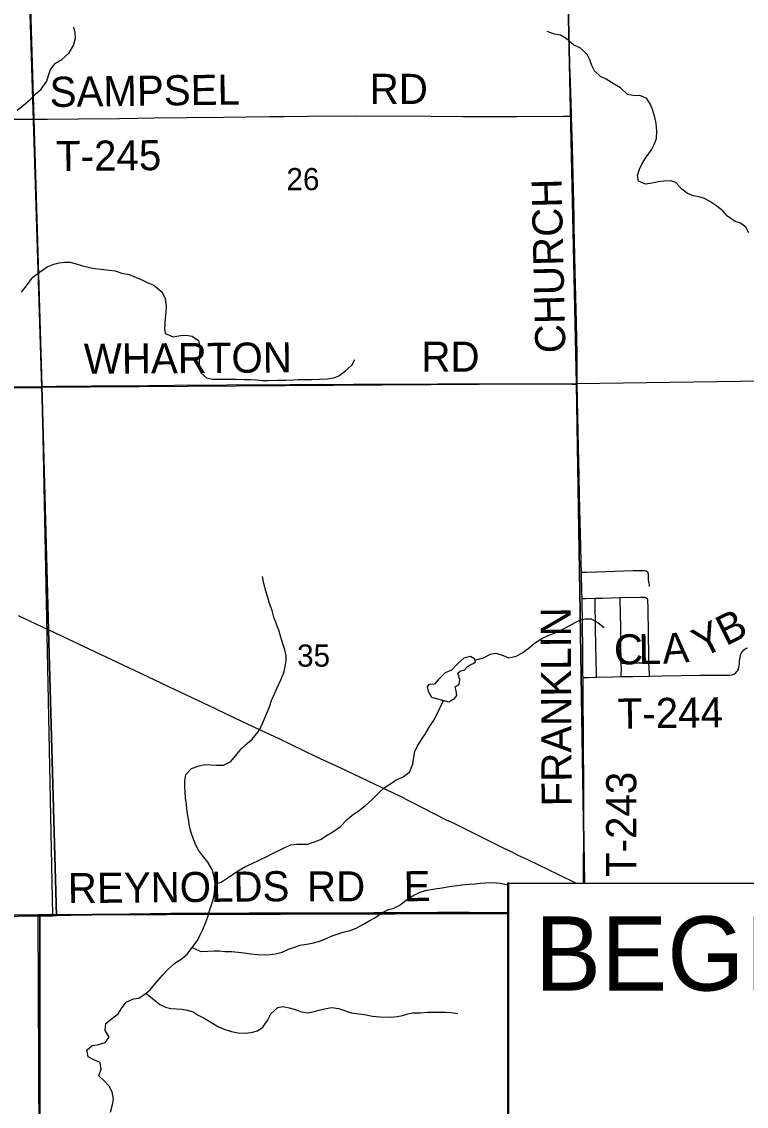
# Model space of a CAD drawing. Extents: x 0 to 34, y 0 to 22.
# Drawn here: x 3.396 to 4.763, y 17.915 to 19.961 of the extents above; entities that cross this region are included whole.
import ezdxf

# ---------------------------------------------------------------- set-up
doc = ezdxf.new("R2010")
doc.units = 0
for name, color, linetype in [('Default', 7, 'Continuous'), ('GM_X_Minor_Lake', 7, 'Continuous'), ('GM_X_Minor_River', 7, 'Continuous'), ('GM_X_Section', 7, 'Continuous'), ('GM_X_Section_Text', 7, 'Continuous'), ('GM_X_State_Route', 7, 'Continuous'), ('GM_X_Township_Road', 7, 'Continuous'), ('GM_X_Township_Road_Text', 7, 'Continuous')]:
    doc.layers.add(name, color=color, linetype=linetype)

msp = doc.modelspace()

# ---------------------------------------------------------------- linework, layer by layer
at = {"layer": 'Default'}
for points in [[(3.3888, 18.2738), (3.4301, 18.2744), (3.4535, 18.2747), (3.4612, 18.275), (3.4463, 18.8138), (3.4336, 19.2731), (3.4185, 19.7774), (3.4027, 20.3001)], [(3.4027, 20.3001), (3.4185, 19.7774), (3.4336, 19.2731), (3.4463, 18.8138), (3.4612, 18.275), (3.4874, 18.2757), (3.5278, 18.2766), (3.5774, 18.2768), (3.5992, 18.2774), (3.6768, 18.2782), (3.7478, 18.2787), (3.7636, 18.2786), (3.7693, 18.2786), (3.7965, 18.2787), (3.8251, 18.2793), (3.8625, 18.2791), (3.8836, 18.2793), (3.9241, 18.2791), (3.9547, 18.2791), (3.9763, 18.2791), (4.0287, 18.2792), (4.0598, 18.2796), (4.0753, 18.2798), (4.1094, 18.2798), (4.1498, 18.2796), (4.1807, 18.2803), (4.2397, 18.2802), (4.3145, 18.28), (4.3145, 18.3355), (6.2148, 18.3355)], [(3.4297, 17.7382), (3.4301, 18.2744), (3.3888, 18.2738)], [(4.3145, 17.662), (4.3145, 18.28), (4.2397, 18.2802), (4.1807, 18.2803), (4.1498, 18.2796), (4.1094, 18.2798), (4.0753, 18.2798), (4.0598, 18.2796), (4.0287, 18.2792), (3.9763, 18.2791), (3.9547, 18.2791), (3.9241, 18.2791), (3.8836, 18.2793), (3.8625, 18.2791), (3.8251, 18.2793), (3.7965, 18.2787), (3.7693, 18.2786), (3.7636, 18.2786), (3.7478, 18.2787), (3.6768, 18.2782), (3.5992, 18.2774), (3.5774, 18.2768), (3.5278, 18.2766), (3.4874, 18.2757), (3.4612, 18.275), (3.4535, 18.2747), (3.4301, 18.2744), (3.4297, 17.7382)]]:
    msp.add_lwpolyline(points, dxfattribs=at)
msp.add_lwpolyline([(4.3145, 18.3355), (4.3121, 18.3355), (4.3121, 17.6612), (6.2145, 17.6612), (6.2145, 17.662), (4.3145, 17.662)], close=True, dxfattribs=at)
at = {"layer": 'GM_X_Minor_Lake'}
for points in [[(4.2018, 18.6777), (4.2121, 18.6841), (4.2163, 18.6894), (4.2156, 18.6985), (4.2133, 18.7061), (4.2209, 18.711), (4.2225, 18.7201), (4.2188, 18.7319), (4.223, 18.7356), (4.2313, 18.7382), (4.237, 18.7443), (4.2431, 18.7484), (4.2477, 18.7499), (4.2519, 18.7533), (4.25, 18.7587), (4.2421, 18.7632), (4.2299, 18.7599), (4.2185, 18.7497), (4.2066, 18.7372), (4.1945, 18.7327), (4.1815, 18.7191), (4.1743, 18.7112), (4.164, 18.7105), (4.1606, 18.7059), (4.1624, 18.698), (4.1685, 18.6862)], [(4.1685, 18.6862), (4.2018, 18.6777)]]:
    msp.add_lwpolyline(points, dxfattribs=at)
at = {"layer": 'GM_X_Minor_River'}
for points in [[(3.3872, 19.7938), (3.3986, 19.8024), (3.4131, 19.8149), (3.4227, 19.8243), (3.4326, 19.833), (3.4429, 19.8482), (3.4463, 19.8591), (3.4502, 19.8701), (3.4597, 19.8822), (3.4712, 19.8894), (3.4856, 19.9015), (3.4937, 19.9155), (3.4971, 19.9295), (3.4964, 19.9397), (3.4938, 19.95)], [(4.63, 19.6575), (4.6205, 19.6602), (4.6068, 19.6599), (4.5966, 19.6588), (4.5852, 19.6558), (4.5723, 19.654), (4.559, 19.6598), (4.5576, 19.6704), (4.561, 19.6825), (4.5664, 19.6928), (4.574, 19.7049), (4.5836, 19.7189), (4.5886, 19.7287), (4.5932, 19.7405), (4.594, 19.7534), (4.5926, 19.7685), (4.5903, 19.7807), (4.5855, 19.7948), (4.5817, 19.8043), (4.5753, 19.8157), (4.5621, 19.8214), (4.5522, 19.8207), (4.5386, 19.8231), (4.5253, 19.8357), (4.5132, 19.8429), (4.4981, 19.8521), (4.4879, 19.8571), (4.4762, 19.8678), (4.4713, 19.8777), (4.4675, 19.8883), (4.4627, 19.8986), (4.4498, 19.9108), (4.4369, 19.9169), (4.4237, 19.928), (4.412, 19.9353), (4.401, 19.9368), (4.387, 19.9422)], [(4.7676, 19.562), (4.762, 19.573), (4.7518, 19.5803), (4.7415, 19.5834), (4.7275, 19.5937), (4.7185, 19.604), (4.7071, 19.6127), (4.6939, 19.6215), (4.6837, 19.6269), (4.6738, 19.63), (4.6632, 19.6323), (4.6515, 19.6365), (4.6413, 19.6446), (4.63, 19.6575)], [(3.3951, 19.4502), (3.4065, 19.4646), (3.4168, 19.4786), (3.4294, 19.4884), (3.4435, 19.4982), (3.4564, 19.5035), (3.4663, 19.5057), (3.4769, 19.5071), (3.4868, 19.5067), (3.4985, 19.504), (3.5106, 19.5002), (3.5235, 19.4967), (3.5341, 19.4951), (3.5448, 19.4939), (3.5614, 19.4916), (3.5721, 19.4904), (3.5846, 19.4865), (3.5982, 19.4834), (3.6107, 19.4788), (3.6209, 19.4742), (3.6327, 19.4688), (3.6448, 19.4634), (3.6607, 19.4501), (3.6663, 19.4387), (3.6681, 19.4227), (3.6677, 19.4125), (3.6665, 19.4011), (3.6649, 19.3821), (3.6667, 19.3726), (3.6815, 19.3661), (3.6952, 19.3687), (3.7058, 19.369), (3.7175, 19.3671), (3.7293, 19.359), (3.7319, 19.3469), (3.731, 19.3313), (3.7306, 19.3214), (3.7306, 19.3112), (3.7335, 19.2983), (3.7441, 19.2887), (3.7566, 19.2864), (3.7707, 19.286), (3.7801, 19.2863), (3.7999, 19.2862), (3.8154, 19.2857), (3.8276, 19.2857), (3.8386, 19.2849), (3.8499, 19.284), (3.8602, 19.2836), (3.878, 19.2843), (3.894, 19.2842), (3.9076, 19.2853), (3.9175, 19.2856), (3.9304, 19.2859), (3.9429, 19.2859), (3.9577, 19.2862), (3.9721, 19.2869), (3.9843, 19.2891), (3.9938, 19.2925), (4.0067, 19.3019), (4.0186, 19.3128), (4.0243, 19.3231)], [(3.5213, 18.0083), (3.5187, 18.0205), (3.5287, 18.0295), (3.5385, 18.031), (3.553, 18.0351), (3.5606, 18.0449), (3.5535, 18.0579), (3.5547, 18.0712), (3.5676, 18.0817), (3.5775, 18.0893), (3.584, 18.0991), (3.5928, 18.1112), (3.6065, 18.1172), (3.6167, 18.1187), (3.6285, 18.127), (3.638, 18.1345), (3.6487, 18.1478), (3.6621, 18.1625), (3.6705, 18.1723), (3.6846, 18.1848), (3.6983, 18.1935), (3.7086, 18.2021), (3.7193, 18.2169), (3.7273, 18.2275), (3.7323, 18.2381), (3.7372, 18.2483), (3.7434, 18.2623), (3.7468, 18.2722), (3.7503, 18.2832), (3.753, 18.293), (3.7569, 18.304), (3.7596, 18.3165), (3.7604, 18.326), (3.7608, 18.3355), (3.7586, 18.3477), (3.7549, 18.3613), (3.747, 18.3754), (3.7371, 18.388), (3.7292, 18.3979), (3.724, 18.4074), (3.7198, 18.4188), (3.7157, 18.4314), (3.7124, 18.4424), (3.7102, 18.4568), (3.7079, 18.4701), (3.7065, 18.4838), (3.705, 18.4963), (3.7043, 18.5077), (3.7036, 18.518), (3.7033, 18.5275), (3.7052, 18.5404), (3.7159, 18.5517), (3.7307, 18.557), (3.7421, 18.5596), (3.7528, 18.5591), (3.763, 18.5583), (3.7767, 18.5582), (3.7904, 18.5654), (3.8022, 18.5794), (3.8106, 18.5896), (3.8209, 18.5994), (3.8304, 18.607), (3.8418, 18.6209), (3.8472, 18.6312), (3.853, 18.6444), (3.858, 18.6565), (3.8629, 18.6683), (3.8668, 18.68), (3.8729, 18.6929), (3.8779, 18.7043), (3.8848, 18.7191), (3.8906, 18.7342), (3.8929, 18.7444), (3.8945, 18.7558), (3.8945, 18.7653), (3.8923, 18.7756), (3.8886, 18.7874), (3.8848, 18.7995), (3.8807, 18.8128), (3.8751, 18.8273), (3.8717, 18.8372), (3.868, 18.8497), (3.8635, 18.863), (3.8598, 18.8744), (3.856, 18.8862), (3.8527, 18.9007), (3.8497, 18.914)], [(4.2508, 18.7564), (4.2671, 18.7605), (4.2804, 18.7676), (4.2899, 18.7698), (4.3039, 18.7648), (4.3149, 18.761), (4.3286, 18.764), (4.3392, 18.7696), (4.3506, 18.7775), (4.3632, 18.7881), (4.3784, 18.7979), (4.391, 18.8035), (4.4062, 18.8099), (4.4165, 18.8148), (4.4271, 18.8204), (4.4401, 18.8276), (4.4499, 18.8321), (4.4594, 18.8343), (4.4701, 18.8343), (4.4829, 18.827), (4.4946, 18.8178)], [(3.7607, 18.3342), (3.7722, 18.3377), (3.7855, 18.3464), (3.7954, 18.3532), (3.8061, 18.3603), (3.8182, 18.3671), (3.8293, 18.3724), (3.8437, 18.3791), (3.857, 18.3855), (3.8703, 18.3923), (3.881, 18.3972), (3.8924, 18.4028), (3.9034, 18.4077), (3.9141, 18.4095), (3.9235, 18.4091), (3.9346, 18.4094), (3.9478, 18.4136), (3.9593, 18.4181), (3.9718, 18.426), (3.9825, 18.4324), (3.9966, 18.4422), (4.0091, 18.455), (4.019, 18.4641), (4.0305, 18.4712), (4.0434, 18.4814), (4.0564, 18.4927), (4.0701, 18.5067), (4.08, 18.5162), (4.0914, 18.5233), (4.1017, 18.5297), (4.1142, 18.5357), (4.1276, 18.5448), (4.1337, 18.5603), (4.1357, 18.5732), (4.1376, 18.5838), (4.1415, 18.5937), (4.1502, 18.6065), (4.1567, 18.6164), (4.1659, 18.6315), (4.1724, 18.6421), (4.1782, 18.6523), (4.1915, 18.6803)], [(3.7173, 18.2141), (3.7336, 18.2066), (3.7469, 18.2073), (3.7587, 18.208), (3.7682, 18.2079), (3.7788, 18.2071), (3.7913, 18.2067), (3.8042, 18.2055), (3.8152, 18.2043), (3.8281, 18.2027), (3.8398, 18.2011), (3.8546, 18.2003), (3.8645, 18.201), (3.8748, 18.2025), (3.8873, 18.2058), (3.8991, 18.2111), (3.9101, 18.2152), (3.9211, 18.2186), (3.9333, 18.2208), (3.9439, 18.2226), (3.9583, 18.2264), (3.9686, 18.2305), (3.9812, 18.2361), (3.9926, 18.2402), (4.0024, 18.2432), (4.0153, 18.2466), (4.0264, 18.2507), (4.0408, 18.2586), (4.0526, 18.265), (4.0621, 18.2703), (4.0762, 18.2801), (4.088, 18.2861), (4.0975, 18.2883), (4.1093, 18.2943), (4.1188, 18.3015), (4.1344, 18.3124), (4.1477, 18.3188), (4.1599, 18.3226), (4.1751, 18.3248), (4.1891, 18.327), (4.2024, 18.3296), (4.2119, 18.3307), (4.2263, 18.3325), (4.24, 18.3336), (4.251, 18.3343), (4.2605, 18.3354), (4.2708, 18.3364), (4.2844, 18.3371), (4.2984, 18.3355), (4.3136, 18.3324), (4.3145, 18.332)], [(3.6302, 18.1283), (3.6418, 18.1186), (3.6565, 18.1071), (3.6671, 18.1021), (3.6773, 18.0994), (3.688, 18.0986), (3.6978, 18.0978), (3.7081, 18.0962), (3.719, 18.0928), (3.7289, 18.087), (3.7399, 18.0809), (3.7554, 18.0717), (3.766, 18.0656), (3.7788, 18.0598), (3.7913, 18.056), (3.8042, 18.0536), (3.816, 18.0528), (3.8285, 18.0539), (3.8403, 18.0573), (3.8506, 18.064), (3.8594, 18.0765), (3.8659, 18.0894), (3.8788, 18.1011), (3.8891, 18.1029), (3.9001, 18.1006), (3.9095, 18.0983), (3.9236, 18.0933), (3.9361, 18.0913), (3.9475, 18.0936), (3.957, 18.0962), (3.9668, 18.0988), (3.9805, 18.1014), (3.9934, 18.099), (4.0044, 18.0956), (4.0173, 18.0913), (4.0317, 18.0893), (4.0427, 18.0882), (4.0578, 18.085), (4.0711, 18.0838), (4.0939, 18.083), (4.1041, 18.0841), (4.1144, 18.0863), (4.1239, 18.0893), (4.1337, 18.0911), (4.1482, 18.0914), (4.1611, 18.0921), (4.1721, 18.0921), (4.1846, 18.0924), (4.1956, 18.0923), (4.2062, 18.0915), (4.2184, 18.09)], [(3.563, 17.9037), (3.5668, 17.9181), (3.5688, 17.9284), (3.5662, 17.9424), (3.5609, 17.9527), (3.5522, 17.9622), (3.5413, 17.9722), (3.5459, 17.9847), (3.5437, 17.9976), (3.5316, 18.0026), (3.5213, 18.0083)]]:
    msp.add_lwpolyline(points, dxfattribs=at)
at = {"layer": 'GM_X_Section'}
for points in [[(3.4017, 20.2979), (3.4336, 19.2705), (2.4218, 19.2622), (2.3914, 20.2927)], [(4.4204, 20.2835), (4.4424, 19.2777), (3.4336, 19.2705), (3.4017, 20.2979)], [(5.4429, 20.296), (5.4558, 19.2921), (4.4424, 19.2777), (4.4204, 20.2835)], [(5.4633, 18.3355), (5.4558, 19.2921), (4.4424, 19.2777), (4.4577, 18.3355)], [(4.4577, 18.3355), (4.4424, 19.2777), (3.4336, 19.2705), (3.4536, 18.2761), (4.3145, 18.2784), (4.3145, 18.3355)], [(3.4336, 19.2705), (3.4536, 18.2761), (3.4263, 18.2757), (2.4434, 18.2628), (2.4218, 19.2622)], [(2.4116, 18.261), (2.4434, 18.2628), (3.4263, 18.2757), (3.4308, 17.2748), (2.406, 17.2639)], [(4.3145, 18.2784), (3.4536, 18.2761), (3.4263, 18.2757), (3.4308, 17.2748), (4.4385, 17.29), (4.4398, 17.662), (4.3145, 17.662)]]:
    msp.add_lwpolyline(points, close=True, dxfattribs=at)
at = {"layer": 'GM_X_State_Route'}
msp.add_line((3.4456, 18.8137), (3.3898, 18.8402), dxfattribs=at)
msp.add_lwpolyline([(4.4409, 18.3355), (4.4076, 18.352), (4.3714, 18.3698), (4.352, 18.3793), (4.3439, 18.3828), (4.3325, 18.3876), (4.3199, 18.3946), (4.306, 18.4012), (4.2896, 18.4095), (4.2528, 18.4272), (4.2114, 18.4481), (4.1974, 18.4547), (4.1531, 18.4772), (4.1088, 18.4997), (4.0613, 18.5227), (3.9966, 18.5532), (3.9515, 18.5741), (3.8815, 18.6077), (3.8477, 18.6236), (3.8112, 18.6408), (3.7495, 18.6702), (3.6736, 18.7059), (3.6203, 18.7314), (3.522, 18.7779), (3.4465, 18.8133), (3.4456, 18.8137)], dxfattribs=at)
at = {"layer": 'GM_X_Township_Road'}
for points in [[(4.4332, 19.7821), (4.4329, 19.7864), (4.4314, 19.8268), (4.429, 19.8983), (4.428, 19.948), (4.4267, 20.0039), (4.4241, 20.0971), (4.4225, 20.1624), (4.4203, 20.2338), (4.4194, 20.2711), (4.4194, 20.2841)], [(3.4445, 19.7769), (3.5028, 19.7773), (3.5805, 19.7782), (3.6458, 19.779), (3.708, 19.7798), (3.7764, 19.7807), (3.8635, 19.7819), (3.8915, 19.782), (3.935, 19.7825), (4.0252, 19.7829), (4.1683, 19.7822), (4.2273, 19.782), (4.33, 19.7819), (4.417, 19.7823), (4.4264, 19.7821), (4.4332, 19.7821)], [(3.2383, 19.7764), (3.2479, 19.7766), (3.2634, 19.7769), (3.3877, 19.777), (3.4187, 19.7769)], [(3.4187, 19.7769), (3.4375, 19.7768), (3.4445, 19.7769)], [(4.4438, 19.277), (4.4434, 19.3343), (4.4421, 19.3934), (4.44, 19.4896), (4.4386, 19.5477), (4.4382, 19.5725), (4.438, 19.5877), (4.4381, 19.5938), (4.4362, 19.6683), (4.435, 19.7243), (4.4332, 19.7821)], [(3.1716, 19.2703), (3.1803, 19.2705), (3.1989, 19.2711), (3.2331, 19.2711), (3.2952, 19.2714), (3.3605, 19.2717), (3.4338, 19.2725)], [(3.4338, 19.2725), (3.4506, 19.2727), (3.4616, 19.2728)], [(3.4616, 19.2728), (3.5283, 19.2737), (3.5873, 19.2739), (3.684, 19.2752), (3.7832, 19.2753), (3.9013, 19.2765), (3.9145, 19.2765), (3.9261, 19.2765), (3.9634, 19.2766), (4.0098, 19.2765), (4.0217, 19.2766), (4.0398, 19.2766), (4.0599, 19.2768), (4.0899, 19.277), (4.1799, 19.2776), (4.2451, 19.2778), (4.3698, 19.2776), (4.4344, 19.277), (4.4438, 19.277)], [(4.4529, 18.8723), (4.4524, 18.8844), (4.4519, 18.9224), (4.4514, 18.9397), (4.4504, 18.9708), (4.4492, 19.0174), (4.4482, 19.0671), (4.4474, 19.1044), (4.4461, 19.1572), (4.4438, 19.277)], [(4.4519, 18.9224), (4.4613, 18.9223), (4.4801, 18.9226), (4.5488, 18.9253), (4.5706, 18.9251), (4.5737, 18.9245), (4.5762, 18.9228), (4.5775, 18.92), (4.5778, 18.9169), (4.5778, 18.9075), (4.5781, 18.9044), (4.5793, 18.8983), (4.5797, 18.8952)], [(4.4529, 18.8723), (4.4602, 18.8726), (4.4778, 18.8731), (4.4912, 18.8735), (4.5247, 18.8744), (4.5626, 18.8754), (4.5705, 18.8752), (4.5721, 18.8748), (4.573, 18.8744), (4.5738, 18.8739), (4.5746, 18.8733), (4.5755, 18.8725)], [(4.455, 18.7238), (4.4546, 18.7295), (4.4543, 18.7657), (4.4536, 18.834), (4.4531, 18.862), (4.4529, 18.8723)], [(4.48, 18.7241), (4.4799, 18.7311), (4.4793, 18.756), (4.4784, 18.8153), (4.4778, 18.8682), (4.4778, 18.8731)], [(4.5269, 18.7252), (4.5269, 18.731), (4.527, 18.7373), (4.5268, 18.7503), (4.5259, 18.7904), (4.5257, 18.8185), (4.5248, 18.8685), (4.5247, 18.8744)], [(4.58, 18.7263), (4.5798, 18.73), (4.5791, 18.7513), (4.5789, 18.7688), (4.578, 18.8021), (4.5774, 18.858), (4.577, 18.8665), (4.5766, 18.8698), (4.5755, 18.8725)], [(4.48, 18.7241), (4.5111, 18.7248), (4.5269, 18.7252), (4.5484, 18.7257), (4.58, 18.7263), (4.6042, 18.7267), (4.6756, 18.7277), (4.7128, 18.7277), (4.7284, 18.7277), (4.7315, 18.7279), (4.7345, 18.7285), (4.7375, 18.7293), (4.7403, 18.7306), (4.7428, 18.7324), (4.7449, 18.7346), (4.7466, 18.7371), (4.7479, 18.7399), (4.7487, 18.7429), (4.7493, 18.7459), (4.7497, 18.7491), (4.7501, 18.7553), (4.7508, 18.7615), (4.7514, 18.7645), (4.7523, 18.7675), (4.7535, 18.7703), (4.7552, 18.7729), (4.7572, 18.7753), (4.7596, 18.7772), (4.7623, 18.7787), (4.7652, 18.7797)], [(4.5268, 18.7503), (4.5339, 18.7505), (4.5582, 18.7511), (4.5643, 18.7512), (4.5791, 18.7513)], [(4.455, 18.7238), (4.4646, 18.7239), (4.477, 18.724), (4.48, 18.7241)], [(4.4556, 18.3355), (4.4558, 18.346), (4.4563, 18.4393), (4.456, 18.5108), (4.4558, 18.6071), (4.4551, 18.6942), (4.4551, 18.7153), (4.455, 18.7238)], [(3.0684, 18.2709), (3.0845, 18.2708), (3.143, 18.2718), (3.1927, 18.2718), (3.2516, 18.2718), (3.3075, 18.2723), (3.389, 18.2733), (3.4303, 18.2739)], [(3.4303, 18.2739), (3.4537, 18.2742), (3.4614, 18.2744)], [(3.4614, 18.2744), (3.4876, 18.2751), (3.528, 18.2761), (3.5776, 18.2763), (3.5994, 18.2768), (3.677, 18.2776), (3.748, 18.2781), (3.7638, 18.2781), (3.7695, 18.278), (3.7967, 18.2781), (3.8253, 18.2787), (3.8627, 18.2785), (3.8838, 18.2787), (3.9244, 18.2785), (3.9549, 18.2786), (3.9766, 18.2785), (4.029, 18.2787), (4.06, 18.2791), (4.0755, 18.2793), (4.1097, 18.2793), (4.15, 18.279), (4.181, 18.2797), (4.2399, 18.2796), (4.3145, 18.2795)]]:
    msp.add_lwpolyline(points, dxfattribs=at)

# ---------------------------------------------------------------- texts
at = {"layer": 'Default'}
msp.add_text('BEGIN ACQUISITION', height=0.14, dxfattribs=at).set_placement((4.3638, 18.1331))
at = {"layer": 'GM_X_Section_Text'}
for s, p in [('26', (3.8952, 19.6427)), ('35', (3.9152, 18.744))]:
    msp.add_text(s, height=0.04186, rotation=0, dxfattribs=at).set_placement(p)
at = {"layer": 'GM_X_Township_Road_Text'}
for s, height, rotation, p in [('SAMPSEL', 0.05682, 0.7605, (3.4488, 19.7996)), ('RD', 0.05682, 0, (4.0523, 19.8054)), ('T-245', 0.05682, 0.5599, (3.4608, 19.6786)), ('CHURCH', 0.05682, 91.3134, (4.4216, 19.3359)), ('WHARTON', 0.05682, 0.4025, (3.5131, 19.2963)), ('RD', 0.05682, 0, (4.1498, 19.3004)), ('FRANKLIN', 0.05682, 90.2691, (4.4333, 18.4805)), ('B', 0.0568, 26.5912, (4.7241, 18.7822)), ('Y', 0.0568, 27.0952, (4.6797, 18.7595)), ('C', 0.0568, 0.8782, (4.5134, 18.7479)), ('L', 0.0568, 0.8791, (4.56, 18.7487)), ('A', 0.0568, 3.8511, (4.6057, 18.7494)), ('T-244', 0.05682, 0.8211, (4.5205, 18.627)), ('T-243', 0.05682, 90, (4.5551, 18.3473)), ('REYNOLDS', 0.05682, 0.5128, (3.483, 18.2979)), ('RD', 0.05682, 0, (3.934, 18.3013)), ('E', 0.0568, 0.9428, (4.1167, 18.3013))]:
    msp.add_text(s, height=height, rotation=rotation, dxfattribs=at).set_placement(p)

doc.saveas('drawing.dxf')
